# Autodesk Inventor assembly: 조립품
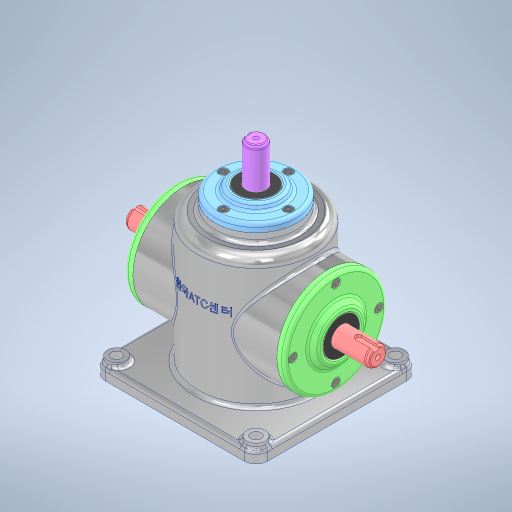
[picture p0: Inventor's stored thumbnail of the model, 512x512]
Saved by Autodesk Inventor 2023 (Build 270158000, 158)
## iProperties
Created: 2025-05
Part Number: 조립품
Document SubType Name: Assembly
Designer: User
Author: User
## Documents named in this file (13)
- C:\Users\User\Desktop\750505V1001\조립품.iam
- C:\Users\User\Desktop\750505V1001\본체.ipt
- C:\Users\User\Desktop\750505V1001\측면 커버.ipt
- C:\Users\User\Desktop\750505V1001\깊은 홈 볼 베어링 6203.ipt
- C:\Users\User\Desktop\750505V1001\오일 실 17 32 8.ipt
- C:\Users\User\Desktop\750505V1001\메인 축.ipt
- C:\Users\User\Desktop\750505V1001\평행 키 5x5.ipt
- C:\Users\User\Desktop\750505V1001\메인 베벨기어.ipt
- C:\Users\User\Desktop\750505V1001\6각 구멍붙이 볼트 M4-10L.ipt
- C:\Users\User\Desktop\750505V1001\윗 커버.ipt
- C:\Users\User\Desktop\750505V1001\서브 축.ipt
- C:\Users\User\Desktop\750505V1001\평행 키 4x4.ipt
- C:\Users\User\Desktop\750505V1001\서브 베벨기어.ipt
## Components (12 placed, 1 different names)
1. 6각 구멍붙이 볼트 M4-10L:1
2. 6각 구멍붙이 볼트 M4-10L:2
3. 6각 구멍붙이 볼트 M4-10L:3
4. 6각 구멍붙이 볼트 M4-10L:4
5. 6각 구멍붙이 볼트 M4-10L:5
6. 6각 구멍붙이 볼트 M4-10L:6
7. 6각 구멍붙이 볼트 M4-10L:7
8. 6각 구멍붙이 볼트 M4-10L:8
9. 6각 구멍붙이 볼트 M4-10L:9
10. 6각 구멍붙이 볼트 M4-10L:10
11. 6각 구멍붙이 볼트 M4-10L:11
12. 6각 구멍붙이 볼트 M4-10L:12
